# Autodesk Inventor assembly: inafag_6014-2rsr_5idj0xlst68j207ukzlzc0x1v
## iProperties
Shininess: 64.0
Angle Display Precision: 2
Document Length Units: 11269
Document Angle Units: 11279
Document Time Units: 11290
Document Mass Units: 11283
Document Length Units Precision: 3
Document Angle Units Precision: 2
Compacted: True
Created: 2008-08
Part Number: inafag_6014-2rsr_5idj0xlst68j207ukzlzc0x1v
Document SubType Name: Assembly
Designer: tpomodeler
Density: 0.0
Volumn: 0.0
Area: 0.0
PropertySet Name: Model Information
Control State: 0
Master: False
Checked Out: False
Author: tpomodeler
